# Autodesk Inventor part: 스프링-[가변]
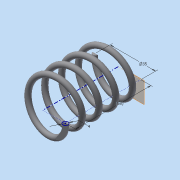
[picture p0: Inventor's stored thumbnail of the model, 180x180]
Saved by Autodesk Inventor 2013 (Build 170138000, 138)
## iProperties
Created: 2015-03
Part Number: 스프링-[가변]
Material: 강철, 탄소
Document SubType Name: Modeling
Designer: Administrator
Density: 7.87 g/cm^3
Mass: 48.2733 g
Surface Area: 62.0009 cm^2
Volume: 6.13384 cm^3
Author: Administrator
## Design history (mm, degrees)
sketch "스케치1"
  geometry: L1 (0, 0)-(17.5, 0); L2 (17.5, 0)-(17.5, 43.5); L3 (17.5, 43.5)-(0, 43.5); L4 (0, 43.5)-(0, 0); C1 r 2 at (17.5, 0)
  constraints: 8 end point, 2 parallel, 1 centre point, 1 coincident, 1 horizontal, 1 perpendicular, 1 point on line
  dimensions: "d0" = 43.5 distance of L1.end L2.end (derived); "d2" = 35 diameter of L2 L4; "d3" = 4 diameter of C1
feature "코일1" sketch "스케치1" pitch "d4" = 10; turns "d6" = 4.5; dims "d5" = 43.5 (= d0), "d7" = 0, angle "d8" = 90 deg, angle "d9" = 90 deg, "d10" = 0, "d11" = 0
sketch "스케치2"
  geometry: L1 (-19.5, 0)-(-15.5, 0) reference; 1 further point
  constraints: 1 horizontal alignment
extrude "돌출1" cut sketch "스케치2" stored distance "d12" = 10; taper "d13" = 0 deg
node "작업 평면1"
sketch "스케치3"
  geometry: L1 (-19.5, 0)-(-15.5, 0) reference; 1 further point
  constraints: 1 horizontal alignment
extrude "돌출2" cut sketch "스케치3" stored distance "d15" = 10; taper "d16" = 0 deg
node "솔리드1"
node "절단 모서리 투영1"
node "절단 모서리 투영2"
other parameters: "d14" = -43.5 (= -d0)
